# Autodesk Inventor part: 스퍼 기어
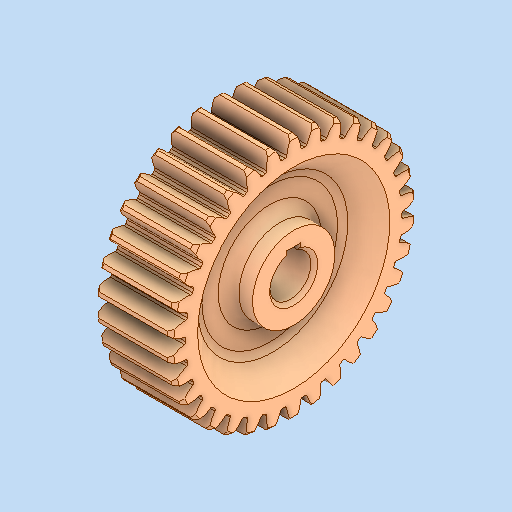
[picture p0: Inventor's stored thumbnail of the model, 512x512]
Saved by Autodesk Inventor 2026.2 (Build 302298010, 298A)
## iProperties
Created: 2026-03
Part Number: 스퍼 기어
Material: 강철, 합금
Document SubType Name: Modeling
Designer: PC-2-03
Density: 7.73 g/cm^3
Appearance: 기본값
Author: jhkim
Sending System: Autodesk Inventor 2026
Preprocessor: ST-DEVELOPER v20.1
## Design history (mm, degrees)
feature "솔리드1"
node "솔리드2"
